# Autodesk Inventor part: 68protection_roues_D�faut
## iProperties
Created: 2011-01
Part Number: 68protection_roues_D�faut
Document SubType Name: Modeling
Designer: eric
Density: 1 g/cm^3
Mass: 108.102 g
Surface Area: 731.26 cm^2
Volume: 108.102 cm^3
Author: eric
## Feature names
1. Base1
